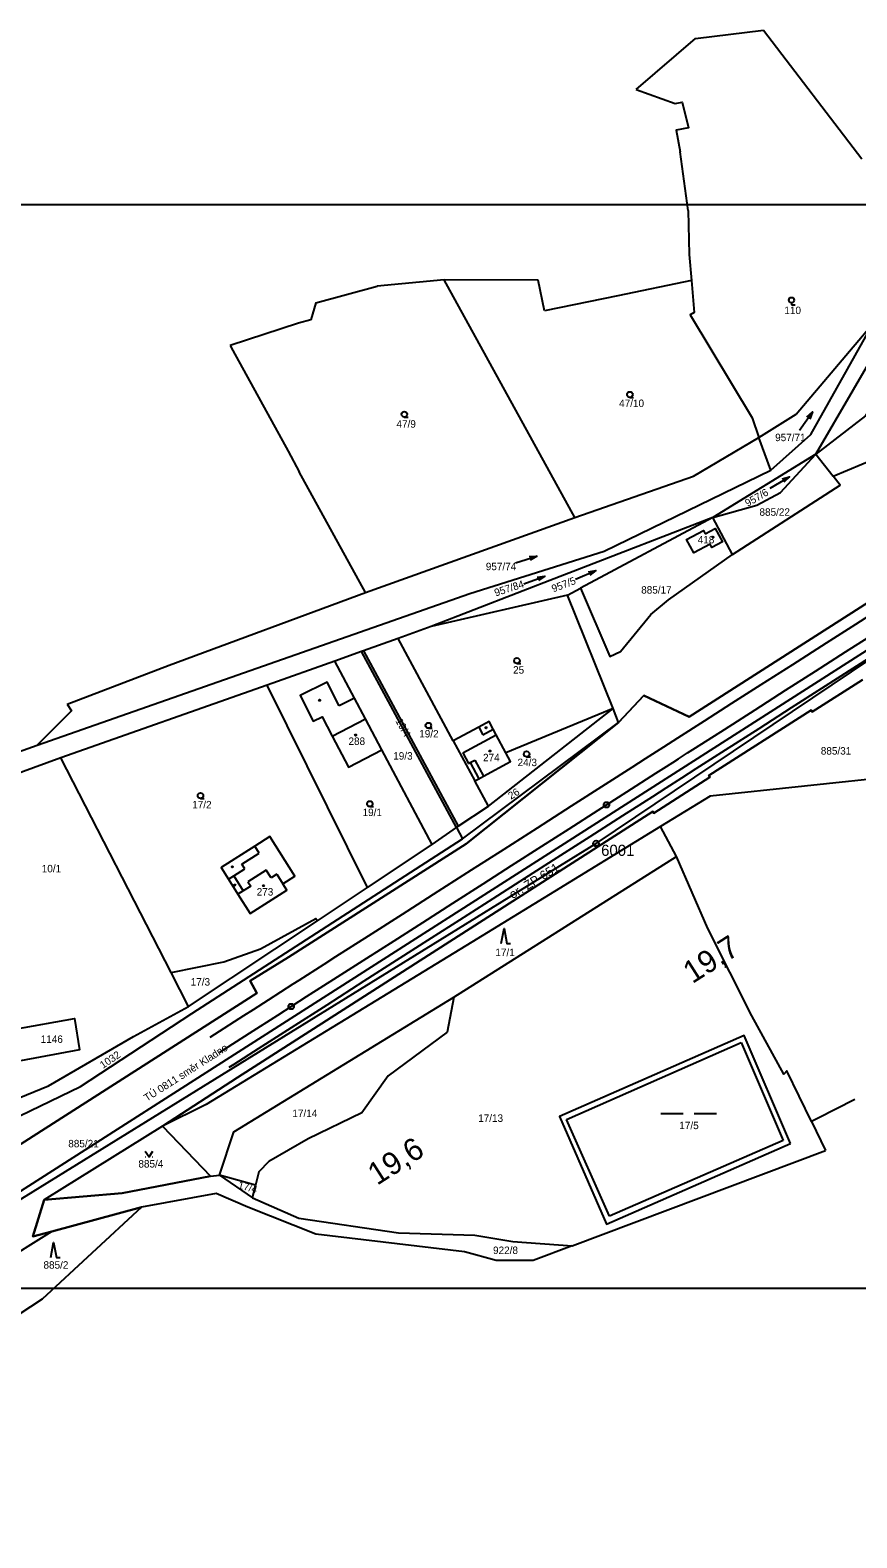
# Model space of a CAD drawing. Extents: x -752210 to -751291, y -1028374 to -1027785.
# Drawn here: x -751867.6 to -751645.7, y -1028255.6 to -1027850.8 of the extents above; entities that cross this region are included whole.
import ezdxf

# ---------------------------------------------------------------- set-up
doc = ezdxf.new("R2010")
doc.units = 0
for name, color, linetype in [('02_Osa_koleje', 7, 'Continuous'), ('03_Staničení', 7, 'Continuous'), ('Vrstva 4', 7, 'Continuous'), ('Vrstva 53', 7, 'Continuous'), ('Vrstva 55', 7, 'Continuous'), ('Vrstva 56', 7, 'Continuous'), ('Vrstva 57', 7, 'Continuous'), ('Vrstva 58', 7, 'Continuous'), ('Vrstva 59', 7, 'Continuous'), ('Vrstva 63', 7, 'Continuous')]:
    doc.layers.add(name, color=color, linetype=linetype)

msp = doc.modelspace()

# ---------------------------------------------------------------- linework, layer by layer
at = {"layer": '02_Osa_koleje'}
for p, q in [((-751645.91, -1028010.23), (-751636.92, -1028004.49)), ((-751653.82, -1028015.29), (-751645.91, -1028010.23)), ((-751648.69, -1028017.73), (-751640.92, -1028012.76)), ((-751662.87, -1028021.07), (-751653.82, -1028015.29)), ((-751646.64, -1028022.11), (-751638.2, -1028016.71)), ((-751671.32, -1028026.46), (-751662.87, -1028021.07)), ((-751656.74, -1028022.88), (-751648.69, -1028017.73)), ((-751664.8, -1028028.03), (-751656.74, -1028022.88)), ((-751655.05, -1028027.47), (-751646.64, -1028022.11)), ((-751679.23, -1028031.51), (-751671.32, -1028026.46)), ((-751673, -1028033.27), (-751664.8, -1028028.03)), ((-751663.19, -1028032.68), (-751655.05, -1028027.47)), ((-751686.59, -1028036.23), (-751679.23, -1028031.51)), ((-751681.21, -1028038.52), (-751673, -1028033.27)), ((-751671.92, -1028038.25), (-751663.19, -1028032.68)), ((-751693.69, -1028040.78), (-751686.59, -1028036.23)), ((-751697.47, -1028043.2), (-751693.69, -1028040.78)), ((-751688.98, -1028043.49), (-751681.21, -1028038.52)), ((-751680.91, -1028044.01), (-751671.92, -1028038.25)), ((-751702.42, -1028046.37), (-751697.47, -1028043.2)), ((-751693.57, -1028046.42), (-751691.1, -1028044.85)), ((-751691.1, -1028044.85), (-751688.98, -1028043.49)), ((-751686.82, -1028047.78), (-751680.91, -1028044.01)), ((-751713.11, -1028053.22), (-751705.97, -1028048.65)), ((-751705.97, -1028048.65), (-751702.42, -1028046.37)), ((-751699.61, -1028050.29), (-751697.44, -1028048.9)), ((-751697.44, -1028048.9), (-751695.1, -1028047.41)), ((-751695.1, -1028047.41), (-751693.57, -1028046.42)), ((-751692.69, -1028051.52), (-751688.81, -1028049.05)), ((-751688.81, -1028049.05), (-751686.82, -1028047.78)), ((-751722.23, -1028059.04), (-751713.11, -1028053.22)), ((-751707.41, -1028055.27), (-751699.61, -1028050.29)), ((-751696.88, -1028054.2), (-751692.69, -1028051.52)), ((-751715.15, -1028060.22), (-751707.41, -1028055.27)), ((-751708.45, -1028061.62), (-751700.46, -1028056.5)), ((-751700.46, -1028056.5), (-751696.88, -1028054.2)), ((-751731.44, -1028064.93), (-751722.23, -1028059.04)), ((-751722.91, -1028065.18), (-751715.15, -1028060.22)), ((-751717.26, -1028067.26), (-751708.45, -1028061.62)), ((-751740.37, -1028070.64), (-751731.44, -1028064.93)), ((-751730.24, -1028069.87), (-751722.91, -1028065.18)), ((-751738.35, -1028075.06), (-751730.24, -1028069.87)), ((-751726.12, -1028072.93), (-751717.26, -1028067.26)), ((-751749.1, -1028076.23), (-751740.37, -1028070.64)), ((-751734.76, -1028078.44), (-751726.12, -1028072.93)), ((-751758.04, -1028081.94), (-751749.1, -1028076.23)), ((-751746.01, -1028079.96), (-751738.35, -1028075.06)), ((-751767.69, -1028088.11), (-751758.04, -1028081.94)), ((-751754.17, -1028085.18), (-751746.01, -1028079.96)), ((-751743.32, -1028083.91), (-751734.76, -1028078.44)), ((-751762.21, -1028090.32), (-751754.17, -1028085.18)), ((-751752.24, -1028089.62), (-751743.32, -1028083.91)), ((-751776.82, -1028093.96), (-751767.69, -1028088.11)), ((-751769.91, -1028095.24), (-751762.21, -1028090.32)), ((-751759.86, -1028094.49), (-751752.24, -1028089.62)), ((-751785.51, -1028099.52), (-751776.82, -1028093.96)), ((-751777.26, -1028099.94), (-751769.91, -1028095.24)), ((-751769.24, -1028100.51), (-751759.86, -1028094.49)), ((-751795.35, -1028105.81), (-751788.71, -1028101.56)), ((-751788.71, -1028101.56), (-751785.51, -1028099.52)), ((-751785.09, -1028104.95), (-751777.26, -1028099.94)), ((-751777.92, -1028106.05), (-751769.24, -1028100.51)), ((-751796.99, -1028106.86), (-751795.35, -1028105.81)), ((-751793.41, -1028110.27), (-751785.09, -1028104.95)), ((-751787.91, -1028112.43), (-751777.92, -1028106.05)), ((-751803.67, -1028111.13), (-751796.99, -1028106.86)), ((-751801.11, -1028115.2), (-751793.41, -1028110.27)), ((-751810.27, -1028115.35), (-751807.69, -1028113.7)), ((-751807.69, -1028113.7), (-751803.67, -1028111.13)), ((-751797.49, -1028118.58), (-751787.91, -1028112.43)), ((-751818.04, -1028120.32), (-751810.27, -1028115.34)), ((-751808.72, -1028120.07), (-751801.11, -1028115.2)), ((-751806.31, -1028124.21), (-751797.49, -1028118.58)), ((-751819.33, -1028121.15), (-751818.04, -1028120.32)), ((-751816.72, -1028125.18), (-751808.72, -1028120.07)), ((-751816.74, -1028125.19), (-751816.72, -1028125.18)), ((-751812.84, -1028128.4), (-751806.31, -1028124.21)), ((-751814.16, -1028129.24), (-751812.84, -1028128.4))]:
    msp.add_line(p, q, dxfattribs=at)
at = {"layer": '03_Staničení'}
for centre in [(-751712.88, -1028058.77), (-751797.54, -1028112.91)]:
    msp.add_circle(centre, 0.75, dxfattribs=at)
at = {"layer": 'Vrstva 4'}
msp.add_lwpolyline([(-751880.79, -1027897.6), (-751466.79, -1027897.6), (-751466.79, -1028188.6), (-751880.79, -1028188.6)], close=True, dxfattribs=at)
at = {"layer": 'Vrstva 53'}
for points in [[(-751890.97, -1028163.13), (-751806.75, -1028109.29), (-751808.53, -1028106.05), (-751798.29, -1028099.68), (-751750.57, -1028069.21), (-751709.61, -1028036.63), (-751702.85, -1028029.39), (-751690.7, -1028035.11), (-751634.83, -1027999.42), (-751532.07, -1027933.64), (-751519.82, -1027926.47), (-751506.87, -1027919.58), (-751494.13, -1027913.25), (-751481.54, -1027906.54), (-751469.19, -1027899.14), (-751466.79, -1027897.6)], [(-751644.14, -1028025.2), (-751657.66, -1028033.82), (-751657.93, -1028033.4), (-751685.36, -1028050.92), (-751685.1, -1028051.35), (-751700.15, -1028061), (-751700.39, -1028060.59), (-751811.98, -1028131.93), (-751832.08, -1028145), (-751819.17, -1028158.43), (-751842.96, -1028162.99), (-751863.83, -1028164.81), (-751866.87, -1028174.68), (-751861.84, -1028173.32), (-751837.73, -1028166.78), (-751864.36, -1028191.47), (-751928.16, -1028233.3)]]:
    msp.add_lwpolyline(points, dxfattribs=at)
at = {"layer": 'Vrstva 55'}
for p, q in [((-751670.74, -1027850.8), (-751644.31, -1027885.35)), ((-751704.87, -1027866.74), (-751694.47, -1027870.45)), ((-751690.99, -1027899.26), (-751693.06, -1027883.49)), ((-751656.71, -1027964.65), (-751615.69, -1027894.18)), ((-751690.99, -1027899.26), (-751690.67, -1027911.02)), ((-751690.67, -1027911.02), (-751690.06, -1027918.02)), ((-751790.91, -1027924.02), (-751774.43, -1027919.56)), ((-751756.49, -1027917.81), (-751774.43, -1027919.56)), ((-751721.34, -1027981.66), (-751756.49, -1027917.81)), ((-751731.23, -1027917.9), (-751756.49, -1027917.81)), ((-751729.53, -1027926.17), (-751731.23, -1027917.9)), ((-751690.06, -1027918.02), (-751709.85, -1027922.12)), ((-751790.91, -1027924.02), (-751792.3, -1027928.54)), ((-751709.85, -1027922.12), (-751729.53, -1027926.17)), ((-751795.59, -1027929.43), (-751813.91, -1027935.42)), ((-751792.3, -1027928.54), (-751795.59, -1027929.43)), ((-751813.91, -1027935.42), (-751813.18, -1027936.76)), ((-751813.18, -1027936.76), (-751798.39, -1027963.79)), ((-751668.79, -1027968.97), (-751672, -1027960.17)), ((-751798.39, -1027963.79), (-751795.36, -1027969.33)), ((-751656.71, -1027964.65), (-751684.34, -1027981.6)), ((-751656.71, -1027964.65), (-751651.99, -1027970.58)), ((-751777.61, -1028001.77), (-751795.36, -1027969.33)), ((-751777.61, -1028001.77), (-751721.34, -1027981.66)), ((-751684.34, -1027981.6), (-751719.87, -1028000.62)), ((-751679.08, -1027991.59), (-751684.34, -1027981.6)), ((-751723.32, -1028002.47), (-751719.87, -1028000.62)), ((-751830.33, -1028021.31), (-751777.61, -1028001.77)), ((-751723.32, -1028002.47), (-751759.96, -1028010.88)), ((-751711.11, -1028032.94), (-751723.32, -1028002.47)), ((-751759.96, -1028010.88), (-751768.84, -1028014.13)), ((-751778.12, -1028017.44), (-751778.69, -1028017.64)), ((-751768.84, -1028014.13), (-751778.12, -1028017.44)), ((-751778.12, -1028017.44), (-751752.67, -1028064.5)), ((-751754, -1028041.6), (-751768.84, -1028014.13)), ((-751857.65, -1028031.73), (-751830.33, -1028021.31)), ((-751785.81, -1028020.18), (-751803.99, -1028026.65)), ((-751778.69, -1028017.64), (-751785.81, -1028020.18)), ((-751780.53, -1028030.11), (-751785.81, -1028020.18)), ((-751753.17, -1028064.84), (-751778.69, -1028017.64)), ((-751803.99, -1028026.65), (-751859.41, -1028046.14)), ((-751777.01, -1028080.95), (-751803.99, -1028026.65)), ((-751702.85, -1028029.39), (-751709.61, -1028036.63)), ((-751780.53, -1028030.11), (-751784.62, -1028032.2)), ((-751744.55, -1028059.1), (-751711.11, -1028032.94)), ((-751711.11, -1028032.94), (-751739.87, -1028044.82)), ((-751709.61, -1028036.63), (-751711.11, -1028032.94)), ((-751751.51, -1028067.92), (-751709.61, -1028036.63)), ((-751709.61, -1028036.63), (-751750.57, -1028069.21)), ((-751754, -1028041.6), (-751748.2, -1028052.33)), ((-751895.64, -1028053.38), (-751865.7, -1028042.71)), ((-751759.72, -1028069.4), (-751773.17, -1028043.99)), ((-751859.41, -1028046.14), (-751881.38, -1028054.14)), ((-751829.79, -1028103.79), (-751859.41, -1028046.14)), ((-751744.55, -1028059.1), (-751748.2, -1028052.33)), ((-751752.67, -1028064.5), (-751744.55, -1028059.1)), ((-751759.72, -1028069.4), (-751753.17, -1028064.84)), ((-751753.17, -1028064.84), (-751752.67, -1028064.5)), ((-751753.17, -1028064.84), (-751751.51, -1028067.92)), ((-751694.07, -1028072.66), (-751698.4, -1028064.61)), ((-751777.01, -1028080.95), (-751759.72, -1028069.4)), ((-751753.83, -1028110.42), (-751694.07, -1028072.66)), ((-751790.46, -1028089.89), (-751777.01, -1028080.95)), ((-751825.11, -1028112.91), (-751790.46, -1028089.89)), ((-751825.11, -1028112.91), (-751829.79, -1028103.79)), ((-751832.08, -1028145), (-751811.98, -1028131.93)), ((-751832.08, -1028145), (-751863.83, -1028164.81)), ((-751832.08, -1028145), (-751819.17, -1028158.43)), ((-751657.84, -1028143.83), (-751654.06, -1028151.61)), ((-751722.1, -1028177.18), (-751654.06, -1028151.61)), ((-751819.17, -1028158.43), (-751816.81, -1028158.16)), ((-751807.12, -1028160.84), (-751816.81, -1028158.16)), ((-751816.81, -1028158.16), (-751807.94, -1028164.26)), ((-751807.94, -1028164.26), (-751807.12, -1028160.84)), ((-751837.73, -1028166.78), (-751861.84, -1028173.32)), ((-751861.84, -1028173.32), (-751876.44, -1028182.41)), ((-751722.1, -1028177.18), (-751732.54, -1028181.1)), ((-751732.54, -1028181.1), (-751742.53, -1028181.08))]:
    msp.add_line(p, q, dxfattribs=at)
for points in [[(-751704.87, -1027866.74), (-751689.01, -1027853.02), (-751670.74, -1027850.8)], [(-751694.47, -1027870.45), (-751692.52, -1027870.09), (-751690.89, -1027877.03), (-751694.15, -1027877.64), (-751693.06, -1027883.49)], [(-751469.19, -1027899.14), (-751481.54, -1027906.54), (-751494.13, -1027913.25), (-751506.87, -1027919.58), (-751519.82, -1027926.47), (-751532.07, -1027933.64), (-751634.83, -1027999.42), (-751690.7, -1028035.11), (-751702.85, -1028029.39)], [(-751690.06, -1027918.02), (-751689.33, -1027926.62), (-751690.4, -1027927.23), (-751673.79, -1027954.88), (-751672, -1027960.17)], [(-751672, -1027960.17), (-751661.99, -1027953.87), (-751641.14, -1027929.37)], [(-751668.79, -1027968.97), (-751658.03, -1027959.34), (-751641.14, -1027929.37)], [(-751626.99, -1027930.26), (-751643.3, -1027954.3), (-751656.71, -1027964.65)], [(-751651.99, -1027970.58), (-751636.62, -1027964.12), (-751616.15, -1027952.42)], [(-751721.34, -1027981.66), (-751689.52, -1027970.51), (-751672, -1027960.17)], [(-751684.34, -1027981.6), (-751672.55, -1027978.29), (-751666.13, -1027974.89), (-751656.71, -1027964.65)], [(-751865.7, -1028042.71), (-751749.56, -1028002.08), (-751713.49, -1027990.7), (-751668.79, -1027968.97)], [(-751679.08, -1027991.59), (-751650.14, -1027972.91), (-751651.99, -1027970.58)], [(-751684.34, -1027981.6), (-751721.79, -1027996.16), (-751725.3, -1027997.51), (-751759.96, -1028010.88)], [(-751686.34, -1027986.01), (-751683.66, -1027984.6), (-751681.77, -1027988.19), (-751684.55, -1027989.66), (-751685.01, -1027988.78), (-751689.45, -1027991.12), (-751691.36, -1027987.53), (-751686.8, -1027985.13), (-751686.34, -1027986.01)], [(-751719.87, -1028000.62), (-751712.01, -1028018.94), (-751709.09, -1028017.63), (-751700.97, -1028007.7), (-751696.27, -1028003.7), (-751679.08, -1027991.59)], [(-751811.98, -1028131.93), (-751700.39, -1028060.59), (-751700.15, -1028061), (-751685.1, -1028051.35), (-751685.36, -1028050.92), (-751657.93, -1028033.4), (-751657.66, -1028033.82), (-751644.14, -1028025.2)], [(-751784.62, -1028032.2), (-751787.87, -1028025.82), (-751795.1, -1028029.46), (-751791.61, -1028036.31), (-751789.26, -1028035.12), (-751786.51, -1028040.34)], [(-751597.31, -1028027.06), (-751634.36, -1028051.12), (-751685.04, -1028056.42), (-751698.4, -1028064.61)], [(-751857.65, -1028031.73), (-751856.49, -1028033.54), (-751865.7, -1028042.71)], [(-751773.17, -1028043.99), (-751777.58, -1028035.66), (-751780.53, -1028030.11)], [(-751739.87, -1028044.82), (-751742.48, -1028039.98), (-751743.32, -1028038.44), (-751744.41, -1028036.42), (-751747.18, -1028037.91), (-751754, -1028041.6)], [(-751786.51, -1028040.34), (-751782.14, -1028048.67), (-751773.17, -1028043.99)], [(-751748.2, -1028052.33), (-751747.12, -1028051.75), (-751745.92, -1028051.1), (-751738.61, -1028047.15), (-751739.87, -1028044.82)], [(-751698.4, -1028064.61), (-751729.61, -1028083.77), (-751749, -1028095.68), (-751820.32, -1028139.23), (-751832.08, -1028145)], [(-751750.57, -1028069.21), (-751798.29, -1028099.68), (-751808.53, -1028106.05), (-751806.75, -1028109.29), (-751890.97, -1028163.13), (-751893.52, -1028163.47)], [(-751884.03, -1028148.84), (-751854.09, -1028134.41), (-751824.25, -1028114.78), (-751751.51, -1028067.92)], [(-751807.31, -1028069.85), (-751816.38, -1028075.6), (-751814.4, -1028078.72), (-751811.83, -1028082.78), (-751808.57, -1028087.93), (-751798.69, -1028081.67), (-751799.78, -1028079.96), (-751796.57, -1028077.93), (-751803.3, -1028067.31), (-751807.31, -1028069.85)], [(-751657.84, -1028143.83), (-751664.47, -1028130.17), (-751665.22, -1028131.05), (-751673.89, -1028115.42), (-751685.71, -1028091.93), (-751694.07, -1028072.66)], [(-751829.79, -1028103.79), (-751815.64, -1028100.96), (-751805.78, -1028097.41), (-751790.88, -1028089.26), (-751790.46, -1028089.89)], [(-751816.81, -1028158.16), (-751812.9, -1028146.59), (-751753.83, -1028110.42)], [(-751753.83, -1028110.42), (-751755.69, -1028119.78), (-751771.54, -1028131.54), (-751778.55, -1028141.46), (-751792.98, -1028148.4), (-751803.51, -1028154.54), (-751806.26, -1028157.26), (-751807.12, -1028160.84)], [(-751886.38, -1028143.87), (-751862.7, -1028134.19), (-751839.92, -1028121.01), (-751825.11, -1028112.91)], [(-751871.76, -1028119), (-751855.74, -1028116.09), (-751854.37, -1028124.51), (-751870.23, -1028127.46), (-751871.76, -1028119)], [(-751663.5, -1028149.71), (-751675.94, -1028120.67), (-751725.5, -1028142.46), (-751712.88, -1028171.35), (-751663.5, -1028149.71)], [(-751646.2, -1028137.9), (-751651.28, -1028140.49), (-751656, -1028142.89), (-751657.84, -1028143.83)], [(-751863.83, -1028164.81), (-751842.96, -1028162.99), (-751819.17, -1028158.43)], [(-751742.53, -1028181.08), (-751751.04, -1028178.81), (-751790.89, -1028174.07), (-751809.18, -1028166.74), (-751817.68, -1028163.14), (-751837.73, -1028166.78)], [(-751837.73, -1028166.78), (-751864.36, -1028191.47), (-751928.16, -1028233.3), (-751967.27, -1028248.1), (-751980.73, -1028255.56)], [(-751861.84, -1028173.32), (-751866.87, -1028174.68), (-751863.83, -1028164.81)], [(-751807.94, -1028164.26), (-751795.47, -1028169.71), (-751768.76, -1028173.66), (-751748.19, -1028174.34), (-751738.05, -1028176.01), (-751722.1, -1028177.18)]]:
    msp.add_lwpolyline(points, dxfattribs=at)
at = {"layer": 'Vrstva 56'}
for p, q in [((-751786.51, -1028040.34), (-751777.58, -1028035.66)), ((-751751.47, -1028044.84), (-751742.48, -1028039.98)), ((-751747.18, -1028037.91), (-751746.09, -1028039.94)), ((-751746.09, -1028039.94), (-751743.32, -1028038.44)), ((-751751.47, -1028044.84), (-751749.93, -1028047.7)), ((-751749.93, -1028047.7), (-751749.45, -1028047.44)), ((-751749.45, -1028047.44), (-751748.25, -1028046.79)), ((-751749.45, -1028047.44), (-751747.12, -1028051.75)), ((-751748.25, -1028046.79), (-751745.92, -1028051.1)), ((-751806.11, -1028071.75), (-751807.31, -1028069.85)), ((-751810.79, -1028074.72), (-751806.11, -1028071.75)), ((-751814.4, -1028078.72), (-751812.97, -1028077.81)), ((-751812.97, -1028077.81), (-751810.02, -1028075.95)), ((-751812.97, -1028077.81), (-751810.4, -1028081.87)), ((-751810.02, -1028075.95), (-751810.79, -1028074.72)), ((-751804.21, -1028076.3), (-751809.16, -1028079.43)), ((-751802.93, -1028078.33), (-751804.21, -1028076.3)), ((-751801.41, -1028077.37), (-751802.93, -1028078.33)), ((-751801.41, -1028077.37), (-751799.78, -1028079.96)), ((-751810.4, -1028081.87), (-751811.83, -1028082.78)), ((-751808.41, -1028080.61), (-751810.4, -1028081.87)), ((-751809.16, -1028079.43), (-751808.41, -1028080.61)), ((-751723.57, -1028143.22), (-751676.75, -1028122.56)), ((-751676.75, -1028122.56), (-751665.43, -1028148.92)), ((-751712.04, -1028169.17), (-751723.57, -1028143.22)), ((-751665.43, -1028148.92), (-751712.04, -1028169.17))]:
    msp.add_line(p, q, dxfattribs=at)
at = {"layer": 'Vrstva 58'}
for p, q in [((-751663.2, -1027923.99), (-751663.2, -1027924.54)), ((-751663.2, -1027924.54), (-751662.2, -1027924.54)), ((-751706.59, -1027949.38), (-751705.59, -1027949.38)), ((-751767.16, -1027954.67), (-751766.16, -1027954.67)), ((-751661.01, -1027958.18), (-751657.56, -1027953.27)), ((-751668.92, -1027973.77), (-751663.77, -1027970.7)), ((-751737.32, -1027993.8), (-751731.6, -1027991.98)), ((-751721.24, -1027998.21), (-751715.7, -1027995.9)), ((-751735.07, -1027999.45), (-751729.44, -1027997.38)), ((-751736.92, -1028020.84), (-751735.92, -1028020.84)), ((-751760.69, -1028038.22), (-751759.69, -1028038.22)), ((-751734.32, -1028045.89), (-751733.32, -1028045.89)), ((-751821.89, -1028057.08), (-751820.89, -1028057.08)), ((-751776.42, -1028059.25), (-751775.42, -1028059.25)), ((-751698.31, -1028141.68), (-751692.31, -1028141.68)), ((-751689.31, -1028141.68), (-751683.31, -1028141.68)), ((-751836.66, -1028153.26), (-751836.56, -1028153.26)), ((-751834.86, -1028153.26), (-751834.76, -1028153.26))]:
    msp.add_line(p, q, dxfattribs=at)
for points in [[(-751659.12, -1027954.62), (-751657.56, -1027953.27), (-751658.3, -1027955.2)], [(-751665.74, -1027971.29), (-751663.77, -1027970.7), (-751665.23, -1027972.15)], [(-751733.66, -1027992.11), (-751731.6, -1027991.98), (-751733.36, -1027993.06)], [(-751717.74, -1027996.21), (-751715.7, -1027995.9), (-751717.36, -1027997.13)], [(-751731.49, -1027997.61), (-751729.44, -1027997.38), (-751731.14, -1027998.54)], [(-751741.12, -1028095.98), (-751740.37, -1028091.98), (-751739.62, -1028095.98), (-751738.62, -1028095.98)], [(-751836.71, -1028151.76), (-751835.71, -1028153.26), (-751834.71, -1028151.76)], [(-751862.07, -1028180.28), (-751861.32, -1028176.28), (-751860.57, -1028180.28), (-751859.57, -1028180.28)]]:
    msp.add_lwpolyline(points, dxfattribs=at)
for centre, radius in [((-751663.2, -1027923.26), 0.725), ((-751706.59, -1027948.63), 0.75), ((-751767.16, -1027953.92), 0.75), ((-751736.92, -1028020.09), 0.75), ((-751760.69, -1028037.47), 0.75), ((-751734.32, -1028045.14), 0.75), ((-751821.89, -1028056.33), 0.75), ((-751776.42, -1028058.5), 0.75)]:
    msp.add_circle(centre, radius, dxfattribs=at)
at = {"layer": 'Vrstva 59'}
for centre in [(-751684.3, -1027986.91), (-751789.9, -1028030.69), (-751780.23, -1028040.05), (-751745.22, -1028038.07), (-751744.16, -1028044.32), (-751813.36, -1028075.42), (-751812.67, -1028080.3), (-751804.96, -1028080.47)]:
    msp.add_circle(centre, 0.175, dxfattribs=at)
at = {"layer": 'Vrstva 63'}
for p, q in [((-751551.77, -1027958.95), (-751975.84, -1028230)), ((-751715.69, -1028069.13), (-751551.77, -1027958.95)), ((-751715.69, -1028069.13), (-751975.84, -1028230)), ((-751715.74, -1028069.13), (-751715.64, -1028069.13))]:
    msp.add_line(p, q, dxfattribs=at)
msp.add_circle((-751715.69, -1028069.13), 0.756, dxfattribs=at)

# ---------------------------------------------------------------- texts
at = {"layer": '02_Osa_koleje'}
msp.add_text('TÚ 0811 směr Kladno', height=2, rotation=32.6028, dxfattribs=at).set_placement((-751836.27, -1028138.5))
at = {"layer": '03_Staničení'}
for s, rotation, p in [('19,7', 32.5978, (-751689.82, -1028106.93)), ('19,6', 32.6004, (-751774.48, -1028161.08))]:
    msp.add_text(s, height=6, rotation=rotation, dxfattribs=at).set_placement(p)
at = {"layer": 'Vrstva 57'}
for s, p in [('110', (-751665.11, -1027927.02)), ('47/10', (-751709.48, -1027951.97)), ('47/9', (-751769.26, -1027957.52)), ('957/71', (-751667.59, -1027961.14)), ('885/22', (-751671.8, -1027981.17)), ('418', (-751688.38, -1027988.58)), ('957/74', (-751745.28, -1027995.78)), ('885/17', (-751703.56, -1028002.07)), ('25', (-751737.96, -1028023.55)), ('288', (-751782.15, -1028042.69)), ('19/2', (-751763.16, -1028040.68)), ('19/3', (-751770.14, -1028046.63)), ('274', (-751746.02, -1028047.07)), ('885/31', (-751655.33, -1028045.28)), ('24/3', (-751736.75, -1028048.38)), ('17/2', (-751824.11, -1028059.72)), ('19/1', (-751778.37, -1028061.79)), ('10/1', (-751864.51, -1028076.89)), ('273', (-751806.8, -1028083.13)), ('17/1', (-751742.71, -1028099.38)), ('17/3', (-751824.52, -1028107.3)), ('1146', (-751864.79, -1028122.68)), ('17/14', (-751797.22, -1028142.59)), ('17/13', (-751747.33, -1028143.88)), ('17/5', (-751693.32, -1028145.84)), ('885/21', (-751857.39, -1028150.72)), ('885/4', (-751838.56, -1028156.15)), ('922/8', (-751743.34, -1028179.36)), ('885/2', (-751864.05, -1028183.3))]:
    msp.add_text(s, height=2, dxfattribs=at).set_placement(p)
for s, rotation, p in [('957/6', 30, (-751674.97, -1027978.83)), ('957/84', 18, (-751742.62, -1028002.85)), ('957/5', 21, (-751727.16, -1028001.77)), ('19/4', 299.3436, (-751769.61, -1028036.25)), ('26', 33, (-751738.49, -1028057.43)), ('1032', 34, (-751848.08, -1028129.69)), ('17/4', 345, (-751811.96, -1028161.71))]:
    msp.add_text(s, height=2, rotation=rotation, dxfattribs=at).set_placement(p)
at = {"layer": 'Vrstva 63'}
for s, height, rotation, p in [('6001', 3, 360, (-751714.31, -1028072.48)), ('or. ŽP 651', 2.4, 31.4743, (-751738.08, -1028084.12))]:
    msp.add_text(s, height=height, rotation=rotation, dxfattribs=at).set_placement(p)

doc.saveas('drawing.dxf')
